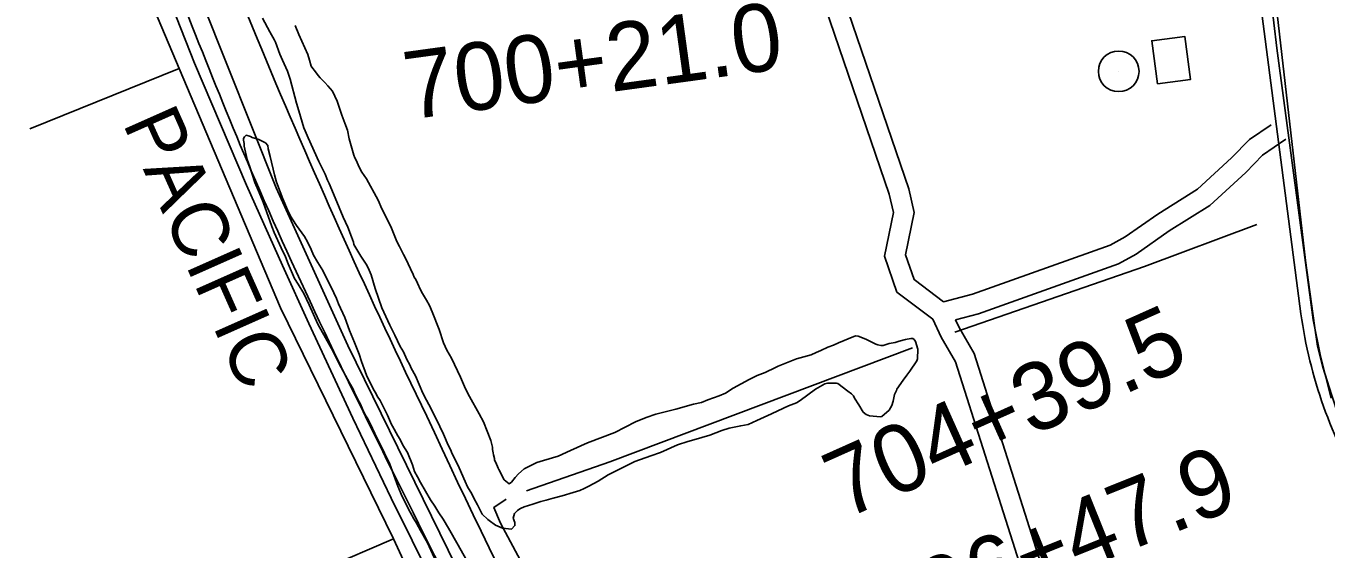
# Model space of a CAD drawing. Extents: x 3161564 to 3199464, y 849354 to 874788.
# Drawn here: x 3172800 to 3174720, y 859480 to 860252 of the extents above; entities that cross this region are included whole.
import ezdxf

# ---------------------------------------------------------------- set-up
doc = ezdxf.new("R2010")
doc.units = 0
for name, color, linetype in [('V-BLDG-OTLN', 7, 'Continuous'), ('V-LEVE-TOET', 7, 'Continuous'), ('V-RAIL-IDEN', 7, 'Continuous'), ('V-RAIL-TRAK', 7, 'Continuous'), ('V-ROAD-CNTR', 7, 'Continuous'), ('V-SITE-VEGE', 7, 'Continuous'), ('V-SURV-IDEN', 7, 'Continuous'), ('V-TOPO-SHOR', 7, 'Continuous'), ('V-TOPO-TOWR', 7, 'Continuous')]:
    doc.layers.add(name, color=color, linetype=linetype)

msp = doc.modelspace()

# ---------------------------------------------------------------- linework, layer by layer
at = {"layer": 'V-BLDG-OTLN'}
msp.add_lwpolyline([(3174470.1, 860167), (3174461.8, 860230.6), (3174510.5, 860237), (3174518.8, 860173.3)], close=True, dxfattribs=at)
at = {"layer": 'V-LEVE-TOET'}
msp.add_lwpolyline([(3175459.5, 858433.4), (3175350.4, 858733.6), (3175314.5, 858825.1), (3175277.8, 858898.4), (3175238, 858970.2), (3175193.8, 859031.2), (3175113.9, 859131.1), (3174929.1, 859367), (3174810.7, 859521.6), (3174784.7, 859565), (3174763.7, 859601.7), (3174748.5, 859640.6), (3174737.5, 859676.7), (3174726.8, 859707.8), (3174714.3, 859748.2), (3174706.3, 859779.3), (3174701.8, 859809.9), (3174688.7, 859906), (3174645.1, 860283.3)], dxfattribs=at)
at = {"layer": 'V-RAIL-TRAK'}
msp.add_lwpolyline([(3174157.4, 858064.1), (3174037.2, 858276.4), (3173924.9, 858475.8), (3173766.8, 858756), (3173598.6, 859058.1), (3173559.2, 859126.8), (3173511.6, 859217.6), (3173461.3, 859309.7), (3173401.1, 859429.8), (3173339.3, 859554.9), (3173282.5, 859673), (3173217.6, 859812.9), (3173178.8, 859898.6), (3173125.5, 860017), (3173048.9, 860197.7), (3172969.1, 860400.4)], dxfattribs=at)
at = {"layer": 'V-ROAD-CNTR'}
for points in [[(3174476.9, 861487.7), (3174560.4, 860764.5), (3174681.7, 859827.2)], [(3174154.2, 859844.7), (3174111, 859877.7), (3174098.2, 859914.3), (3174111.1, 859977), (3174103.4, 860011.9), (3173867.2, 860703)], [(3174590.5, 858409.3), (3174560.5, 858478.6), (3174533.5, 858560.8), (3174496.7, 858707.2), (3174456.5, 858843.4), (3174434.7, 858928.7), (3174172, 859756.3), (3174151, 859792.8), (3174138.4, 859819.1), (3174085.6, 859859.3), (3174067.2, 859912.2), (3174080.5, 859976.7), (3174074.4, 860003.8), (3173838.8, 860693.3)], [(3174154.2, 859844.7), (3174197.2, 859856), (3174400.3, 859928.7), (3174422.7, 859940.8), (3174470.8, 859974.6), (3174529.3, 860011.4), (3174579.4, 860057.6), (3174606, 860084.9), (3174638, 860106.6)], [(3174172, 859818.4), (3174206, 859827.3), (3174412.5, 859901.2), (3174438.5, 859915.2), (3174487.4, 859949.6), (3174547.6, 859987.4), (3174600.4, 860036.1), (3174625.3, 860061.8), (3174659.6, 860085)], [(3174616.9, 858423.8), (3174588.6, 858489.2), (3174562.3, 858569.2), (3174525.6, 858715.1), (3174485.4, 858851.3), (3174463.5, 858937), (3174199.7, 859768.5), (3174177.6, 859806.8), (3174172, 859818.4)]]:
    msp.add_lwpolyline(points, dxfattribs=at)
for centre, radius, start, end in [((3183283.6, 864449.8), 10983.6, 199.75531, 205.76161), ((3175389.6, 859928.1), 715, 188.1088, 210.7285), ((3180964.2, 863152.6), 8332.4, 204.65993, 210.57795)]:
    msp.add_arc(centre, radius, start, end, dxfattribs=at)
msp.add_spline([(3172633.8, 861383.8), (3172802.6, 860880.5), (3172972.2, 860440.5), (3173132.3, 860039.3), (3173355.9, 859565.2), (3173614.6, 859060.8), (3173833.8, 858663.3)], degree=3, dxfattribs=at)
at = {"layer": 'V-SITE-VEGE'}
for points in [[(3173503.6, 859510.5), (3173493.3, 859515.1), (3173483.8, 859521.9), (3173482, 859523.1), (3173473.6, 859531.4), (3173466.7, 859545.2), (3173461.3, 859554.6), (3173458.1, 859561.3), (3173452, 859571.8), (3173448.4, 859579.6), (3173439.8, 859599.4), (3173432.6, 859613.7), (3173429.4, 859620.4), (3173426.9, 859626.7), (3173423.3, 859633.1), (3173416.5, 859649.5), (3173405.8, 859672), (3173403.3, 859676.5), (3173398.2, 859686.6), (3173391.4, 859699.7), (3173386, 859710.1), (3173375, 859735.5), (3173368.8, 859747.1), (3173366.7, 859751.6), (3173362.4, 859759.5), (3173357.4, 859771.1), (3173352.7, 859778.9), (3173344.4, 859795.4), (3173341.9, 859801.4), (3173337.3, 859810.3), (3173325.4, 859836.1), (3173315.5, 859864.5), (3173309.6, 859884.6), (3173305.3, 859895.1), (3173302.4, 859900.3), (3173294.4, 859912.3), (3173284.3, 859929.5), (3173283.7, 859932.9), (3173280.8, 859940.7), (3173275.1, 859955.3), (3173268.3, 859969.9), (3173262.3, 859984.4), (3173251.9, 860010.2), (3173247.6, 860019.9), (3173245.1, 860024.8), (3173241.9, 860033.7), (3173232.6, 860052.4), (3173216.5, 860087.2), (3173212.2, 860097.6), (3173210.1, 860102.1), (3173203.1, 860127.1), (3173199.5, 860138.3), (3173190.1, 860173.7), (3173186.2, 860185.6), (3173178.7, 860201.7), (3173175.1, 860210.6), (3173168.4, 860228.6), (3173167, 860231.6), (3173160.1, 860243.9), (3173149.3, 860264.1)], [(3173197.7, 860252.9), (3173203.1, 860239.9), (3173216.3, 860210.3), (3173218.8, 860202.1), (3173221.2, 860193.2), (3173223.8, 860189.8), (3173225.9, 860186.4), (3173231.7, 860179.3), (3173234.3, 860175.9), (3173241.2, 860168.7), (3173246, 860164.2), (3173252.5, 860155.9), (3173259.3, 860141.4), (3173266.4, 860120.5), (3173271, 860108.9), (3173274.9, 860098.5), (3173277.3, 860085.8), (3173284.3, 860061.6), (3173285.7, 860057.8), (3173287.5, 860054.1), (3173291.8, 860044), (3173296.1, 860036.2), (3173302.6, 860026.4), (3173319.9, 859995.3), (3173325.6, 859982.3), (3173330.3, 859972.9), (3173339.6, 859953.5), (3173346.4, 859936.7), (3173347.8, 859934), (3173351.4, 859926.6), (3173357.2, 859915), (3173360.4, 859909.4), (3173371.5, 859885.4), (3173373.3, 859881.3), (3173375.5, 859878), (3173378, 859872.3), (3173382.6, 859862.6), (3173385.5, 859857.4), (3173391.6, 859847.3), (3173396, 859839.4), (3173399.9, 859830.1), (3173410.2, 859803.9), (3173416.6, 859784.2), (3173421.6, 859773.3), (3173428.1, 859761.7), (3173441.7, 859733.7), (3173448.8, 859716.5), (3173454.6, 859704.9), (3173469, 859679.4), (3173475.5, 859667.5), (3173486.1, 859639.8), (3173488.6, 859630.2), (3173488.9, 859626.8), (3173489.9, 859621.6), (3173490.2, 859618.6), (3173491.6, 859613.4), (3173491.9, 859610.8), (3173493.7, 859607.5), (3173496.9, 859599.2), (3173498, 859597), (3173500.5, 859592.9), (3173502, 859589.5), (3173505.9, 859582), (3173513.2, 859576), (3173517, 859578.5), (3173522.3, 859585.5), (3173527.2, 859590.9), (3173535.5, 859598.2), (3173554.2, 859607.6), (3173563.9, 859610.7), (3173585.9, 859617), (3173603.8, 859625.3), (3173628.9, 859636.7), (3173669.2, 859651.6), (3173699.8, 859667.5), (3173715.5, 859674.2), (3173729.7, 859678.8), (3173759.5, 859686.1)], [(3173253.5, 859771.3), (3173230.8, 859812.1), (3173218.3, 859840.5), (3173210.1, 859857), (3173202.1, 859870.8), (3173196.7, 859879.4), (3173187.1, 859901.1), (3173183.5, 859911.2), (3173177.1, 859924.6), (3173166.7, 859947.4), (3173163.1, 859956.4), (3173150.4, 859991.9), (3173142.9, 860009.8), (3173138.2, 860021.4), (3173130.8, 860044.5), (3173128.4, 860051.2), (3173126.6, 860055.3), (3173122.4, 860075), (3173122.1, 860078.7), (3173121.5, 860083.6), (3173121.5, 860086.2), (3173122.7, 860088.4), (3173125.3, 860090.9), (3173131.6, 860089), (3173134.2, 860087.8), (3173144.1, 860084.7), (3173153.7, 860079.7), (3173157.3, 860075.9)], [(3173157.3, 860075.9), (3173157.6, 860070.7), (3173160.8, 860059.6), (3173167, 860032.7), (3173169.8, 860021.9), (3173179.4, 859996.9), (3173186.2, 859980.9), (3173190.8, 859971.5), (3173194.1, 859965.9), (3173199.5, 859957.7), (3173211.5, 859941.5), (3173215.8, 859933.6), (3173221.2, 859922.1), (3173224.7, 859913.8), (3173231.2, 859903), (3173238.5, 859891.4), (3173248.1, 859870.8), (3173250.6, 859866.3), (3173258.5, 859849.9), (3173261.7, 859842), (3173271, 859821.8), (3173277.8, 859802.4), (3173285.3, 859784.9), (3173292, 859767.7), (3173295.6, 859756.9), (3173302.6, 859736.7), (3173312.7, 859716.2), (3173317, 859709), (3173318.8, 859705.3), (3173322.8, 859698.9), (3173333.6, 859677.2), (3173339.6, 859663.8), (3173341.4, 859661.2), (3173349, 859646.9), (3173352.3, 859641.7), (3173356.6, 859633.1), (3173363.1, 859622.2), (3173370.5, 859604.3), (3173373.7, 859594.2), (3173378, 859586.4), (3173382.3, 859577.8), (3173397.5, 859552.3), (3173403.6, 859542.9), (3173409.4, 859533.2), (3173415.9, 859523.8), (3173423.9, 859510.7), (3173438.3, 859485.6), (3173453.8, 859457.2)], [(3173759.5, 859686.1), (3173785.6, 859693.5), (3173797.1, 859696.2), (3173806.8, 859700.2), (3173823.3, 859706.2), (3173832.6, 859710.1), (3173843.8, 859717.4), (3173867.4, 859730.3), (3173879.4, 859736.1), (3173891, 859740.7), (3173906.3, 859747.8), (3173910.4, 859750), (3173937.3, 859760.7), (3173959.3, 859766.6), (3173966.4, 859769.8), (3173973.5, 859773.1), (3173983.9, 859778.1), (3173992.2, 859780.9), (3173999.3, 859784.1), (3174022, 859793.8), (3174025, 859794.8), (3174028.4, 859794.4), (3174039.8, 859789.8), (3174054.5, 859782.5), (3174057.4, 859781.3), (3174061.9, 859780.5), (3174065.2, 859780.4), (3174074.2, 859783.3), (3174083.1, 859785), (3174088.7, 859786.7), (3174098.4, 859789.2), (3174106.2, 859790.9), (3174109.1, 859790.5), (3174111, 859789), (3174112.8, 859786.3), (3174116.3, 859774.8), (3174116.1, 859760.7), (3174114.9, 859757.7), (3174104.6, 859742.3), (3174100.1, 859736.5), (3174094.8, 859729.1), (3174085.6, 859715.9), (3174084.9, 859713.7), (3174082.2, 859708.2), (3174080.2, 859698.2), (3174078.2, 859691.9), (3174074.4, 859685), (3174063.5, 859675.5), (3174061.2, 859675.2), (3174045.3, 859676.5), (3174040.2, 859678.5), (3174035.8, 859681.9), (3174029.6, 859692.8), (3174023.1, 859702.5), (3174021.7, 859705.9), (3174018.8, 859708.9), (3174013.3, 859712.7), (3173998.3, 859724.4), (3173996, 859724.8), (3173993.1, 859724.5), (3173983.4, 859724.7), (3173979.3, 859723.6), (3173965.5, 859715.7), (3173942.6, 859699), (3173937.3, 859695.8), (3173925.8, 859691.1), (3173910.1, 859684), (3173900.3, 859679.3), (3173878.7, 859669.7), (3173866.3, 859663.9), (3173855.2, 859661.9), (3173838, 859658.1), (3173827.2, 859654.6), (3173809.3, 859647.8), (3173785.8, 859640.8), (3173776.9, 859638.4), (3173762, 859633.4), (3173736.9, 859622.3), (3173722.4, 859617.4), (3173698.9, 859608.9), (3173659.6, 859589.5), (3173644.6, 859579.7), (3173631.1, 859572.5), (3173624, 859568.9), (3173617.7, 859566.1), (3173607.6, 859563.3), (3173591.6, 859558.3), (3173578.5, 859554.9), (3173568.1, 859551.7), (3173559.9, 859550), (3173548.4, 859546.1), (3173535.3, 859542.2), (3173530.1, 859539.7), (3173527.5, 859538.3), (3173525.6, 859536.5), (3173521.1, 859532.4), (3173519.1, 859525.1), (3173521.9, 859518.7), (3173521.9, 859514.3), (3173517, 859509.1), (3173503.6, 859510.5)], [(3173404.9, 859461.7), (3173392.7, 859489), (3173382.3, 859506.9), (3173376.5, 859517.8), (3173372.6, 859524.5), (3173367.5, 859534.3), (3173359.3, 859549.6), (3173354.2, 859560.8), (3173348.9, 859572.4), (3173345, 859583.6), (3173337.2, 859604.9), (3173321.4, 859637.8), (3173318.2, 859644.1), (3173315.3, 859650.5), (3173308.9, 859664.3), (3173304.9, 859671.8), (3173301.6, 859676.7), (3173297.3, 859685.3), (3173293.8, 859693.9), (3173292, 859696.9), (3173286.2, 859708.4), (3173282.7, 859717), (3173277.6, 859725.3), (3173262.5, 859753.4), (3173253.5, 859771.3)]]:
    msp.add_lwpolyline(points, dxfattribs=at)
at = {"layer": 'V-TOPO-SHOR'}
for points in [[(3174130.4, 858196.3), (3173893.7, 858622.4), (3173743.7, 858886.2), (3173578.7, 859179.5), (3173435.8, 859452.8), (3173275.5, 859780.2), (3173169.5, 860013.3), (3173061, 860286.1), (3172920.5, 860639.1), (3172839.6, 860873.9), (3172752.4, 861106.2), (3172655.2, 861373.8)], [(3173026.5, 860189.4), (3172964.3, 860336.8), (3172884.4, 860534), (3172752.9, 860915.9), (3172630.4, 861262.3), (3172630.4, 861262.3), (3172607.3, 861326.2)], [(3174593.2, 860669), (3174646.5, 860219.6), (3174699.8, 859818.1), (3174710.5, 859764.8), (3174726.5, 859702.6)], [(3173342.7, 859494.8), (3173175.7, 859835.9), (3173026.5, 860189.4), (3172806.2, 860100.6)], [(3174616.7, 859959.2), (3174450.9, 859897.1), (3174170.9, 859800.3)], [(3174108.5, 859776.7), (3173661.8, 859608.6), (3173539.1, 859565.7)], [(3173508.8, 859553.3), (3173490.7, 859540.8), (3173500.7, 859517.8), (3173621.2, 859292.6), (3173697, 859140.6)], [(3174273.5, 857798.4), (3173998.2, 858297.5), (3173671.3, 858869.5), (3173428, 859310.1), (3173342.7, 859494.8), (3173239.7, 859450.4)]]:
    msp.add_lwpolyline(points, dxfattribs=at)
at = {"layer": 'V-TOPO-TOWR'}
msp.add_line((3174412.9, 860185.4), (3174412.9, 860185.4), dxfattribs=at)
msp.add_circle((3174412.9, 860185.4), 30, dxfattribs=at)

# ---------------------------------------------------------------- texts
at = {"layer": 'V-RAIL-IDEN'}
msp.add_text('PACIFIC', height=83, rotation=293.9616, dxfattribs=at).set_placement((3172942.4, 860109))
at = {"layer": 'V-SURV-IDEN'}
for s, rotation, p in [('700+21.0', 7.8044, (3173365.3, 860113.9)), ('704+39.5', 24.117, (3174008.5, 859522.9)), ('706+47.9', 21.9236, (3174074.2, 859334))]:
    msp.add_text(s, height=100, rotation=rotation, dxfattribs=at).set_placement(p)

doc.saveas('drawing.dxf')
